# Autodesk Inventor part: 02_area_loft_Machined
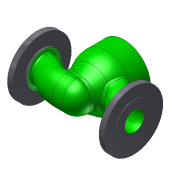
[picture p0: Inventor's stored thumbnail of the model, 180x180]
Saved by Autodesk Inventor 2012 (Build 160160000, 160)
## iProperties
Created: 2007-03
Part Number: 02_area_loft_Machined
Document SubType Name: Modeling
Designer: 43011
Mass: 8830.27 g
Surface Area: 1996.44 cm^2
Volume: 1124.88 cm^3
Density: 7.85 g/cm^3
Material: Steel
Author: 43011
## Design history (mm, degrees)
derived "02_area_loft_casting.ipt"
derived "02_are_loft_def_finished.ipt"
revolve "Revolution2" stored, may be unused: angle "d5" = 90 deg
mirror "Mirror1"
sketch "Sketch7"
  geometry: L1 (-182.013, 0)-(182.01, 0) reference; L2 (0, -113.6)-(0, 139.1) reference; L3 (-37, 103)-(0, 103); L4 (0, 103)-(0, 30); L5 (0, 30)-(-37, 30); L6 (-37, 30)-(-37, 103); L7 (70, 103)-(-70, 103) reference; 1 further point
  constraints: 8 end point, 2 parallel, 1 collinear, 1 horizontal, 1 perpendicular, 1 point on line
  dimensions: "d39" = 74 diameter of L6 L2
revolve "Revolution3" sketch "Sketch7" stored, may be unused: angle "d41" = 90 deg
node "Volumenkörper1"
node "Volumenkörpern"
node "Oberflächenkörpern"
tag "Bezeichnung2"
sketch "Sketch15"
  geometry: L1 (-37.013, 103)-(-37.013, 30); L2 (-37.013, 30)-(0, 30); L3 (70, 103)-(-70, 103) reference; L4 (-37.013, 103)-(0, 103); L5 (0, -121.184)-(0, 184.601) reference; L6 (-182.013, 0)-(182.01, 0) reference; L7 (0, 30)-(0, 103)
  constraints: 8 end point, 2 collinear, 1 parallel, 1 point on line
  dimensions: "d37" = 74.025 diameter of L1 L5; "d38" = 30 distance between parallel lines of L6 L2
sketch "Sketch20"
  geometry: L1 (-128, 77.5)-(-114, 77.5); L2 (-114, 77.5)-(-114, 45); L3 (-114, 45)-(-107, 45); L4 (-107, 45)-(-107, 100.638); L5 (-128, 77.5)-(-128, 48); L6 (-128, 48)-(-130, 48); L7 (-130, 48)-(-130, 0); L8 (0, -81.107)-(0, 145.351); L9 (-205.8, 0)-(205.8, 0); L10 (-130, 0)-(-152.983, 0)
  constraints: 20 end point
feature "DerivedBody::02_area_loft_casting.ipt" dims "d0" = 10
other parameters: "d4" = 90 deg
